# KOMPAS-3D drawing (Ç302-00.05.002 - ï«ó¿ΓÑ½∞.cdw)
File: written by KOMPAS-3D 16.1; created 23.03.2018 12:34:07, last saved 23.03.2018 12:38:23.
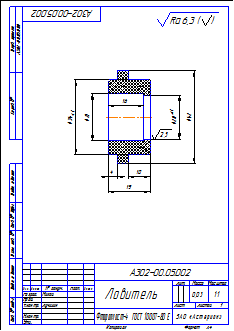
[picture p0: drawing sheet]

Sheet 1: A4, portrait

Title block, sheet 1: name: Ловитель; designation: А302-00.05.002; material: Фторопласт-4  ГОСТ 10007-80 Е; mass: 0,03; scale: 1:1; sheets: 1; organisation: ЗАО «Астерион»; sheet format: A4; stored path: \\192.168.87.28\Konstructor_doc\Мембранные насосы\Мембранный электропривод\А302-00.00.000 - ASTRA-302 (МЭ200)\Чертежи\А302-00.05.002 - Ловитель.cdw; drawn by: Милов; technical control: Лучихин

Views: Вид 1, Местный разрез 1, Спереди, Проекционный вид 2, Вид:1, Вид:2
Referenced files in Z:\Мембранные насосы\Мембранный электропривод\А302-00.00.000 - ASTRA-302 (МЭ200)\3Д\: А302-00.05.002 - Ловитель.m3d
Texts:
  Ra 6,3
  Ra 6,3 ( )
Dimensions and other numbers on the sheet: 20; 21; 16; 10; 4; 19; 34; 42; 2,5; 1:1; 1; 0,03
